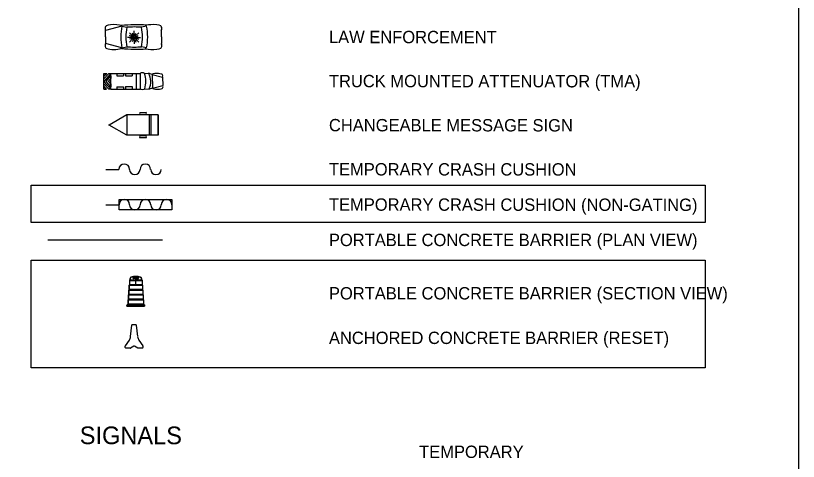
# Model space of a CAD drawing. Extents: x 2486454 to 2490507, y 369321 to 372999.
# Drawn here: x 2488062.6 to 2488506.6, y 370734.3 to 370986.9 of the extents above; entities that cross this region are included whole.
import ezdxf

# ---------------------------------------------------------------- set-up
doc = ezdxf.new("R2010")
doc.units = 0
for name, color, linetype in [('DEV CRASH CUSHION CELL', 7, 'Continuous'), ('Scratch_Level_3', 7, 'Continuous'), ('TC DEV ATTENUATOR', 7, 'Continuous'), ('TC DEV ATTENUATOR TRUCK MOUNTED', 7, 'Continuous'), ('TC DEV BARRIER PCB (UN-ANCHORED)', 7, 'Continuous'), ('TC DEV CMS', 7, 'Continuous'), ('TC DEV LAW ENFORCEMENT', 7, 'Continuous'), ('TC SHEET LAYOUT SHAPE', 7, 'Continuous'), ('TC SHEET TEXT', 7, 'Continuous'), ('TC XS DEVICES', 7, 'Continuous')]:
    doc.layers.add(name, color=color, linetype=linetype)

msp = doc.modelspace()

# ---------------------------------------------------------------- linework, layer by layer
at = {"layer": 'DEV CRASH CUSHION CELL'}
msp.add_line((2488113.69, 370879.76), (2488121.19, 370879.76), dxfattribs=at)
msp.add_lwpolyline([(2488121.19, 370882.76), (2488151.19, 370882.76), (2488151.19, 370876.76), (2488121.19, 370876.76)], close=True, dxfattribs=at)
for centre, start, end in [((2488124.19, 370879.76), 0, 180), ((2488136.19, 370879.76), 0, 180), ((2488148.19, 370879.76), 0, 180), ((2488130.19, 370879.76), 180, 0), ((2488142.19, 370879.76), 180, 0)]:
    msp.add_arc(centre, 3, start, end, dxfattribs=at)
at = {"layer": 'Scratch_Level_3'}
for points in [[(2488071.36, 370890.78), (2488453.76, 370890.78), (2488453.76, 370869.72), (2488071.36, 370869.72)], [(2488071.36, 370848.25), (2488453.76, 370848.25), (2488453.76, 370787.2), (2488071.36, 370787.2)]]:
    msp.add_lwpolyline(points, close=True, dxfattribs=at)
at = {"layer": 'TC DEV ATTENUATOR'}
msp.add_line((2488113.69, 370899.76), (2488121.13, 370899.76), dxfattribs=at)
for centre, radius, start, end in [((2488124.16, 370899.76), 3.03, 359.9999, 179.9999), ((2488130.16, 370899.76), 2.97, 179.9999, 359.9999), ((2488136.13, 370899.76), 3, 359.9999, 179.9999), ((2488142.16, 370899.76), 2.97, 179.9999, 359.9999)]:
    msp.add_arc(centre, radius, start, end, dxfattribs=at)
at = {"layer": 'TC DEV ATTENUATOR TRUCK MOUNTED'}
for p, q in [((2488112.67, 370945.18), (2488112.68, 370954.12)), ((2488112.67, 370951.03), (2488115.44, 370954.12)), ((2488116.64, 370954.12), (2488112.67, 370949.65)), ((2488112.68, 370954.12), (2488112.68, 370952.41)), ((2488112.68, 370954.12), (2488112.68, 370952.41)), ((2488112.68, 370954.12), (2488112.68, 370952.41)), ((2488112.68, 370954.12), (2488112.68, 370952.41)), ((2488112.68, 370952.41), (2488112.68, 370954.12)), ((2488112.68, 370954.12), (2488114.2, 370954.12)), ((2488114.2, 370954.12), (2488112.68, 370952.41)), ((2488113.92, 370949.65), (2488116.64, 370952.73)), ((2488115.44, 370954.12), (2488116.64, 370954.12)), ((2488116.54, 370954.13), (2488133.17, 370954.12)), ((2488116.63, 370945.17), (2488116.64, 370954.12)), ((2488116.64, 370952.73), (2488116.64, 370951.35)), ((2488119.99, 370954.11), (2488119.99, 370952.79)), ((2488119.99, 370952.79), (2488123.74, 370952.79)), ((2488123.74, 370954.1), (2488123.74, 370952.79)), ((2488124.94, 370954.16), (2488124.94, 370952.84)), ((2488124.94, 370952.84), (2488128.68, 370952.84)), ((2488128.69, 370954.15), (2488128.68, 370952.84)), ((2488131, 370954.1), (2488130.99, 370945.16)), ((2488133.17, 370954.12), (2488133.26, 370945.16)), ((2488135.73, 370954.12), (2488137.94, 370954.26)), ((2488139.99, 370953.55), (2488137.94, 370954.26)), ((2488139.97, 370953.55), (2488140.14, 370945.79)), ((2488140, 370953.55), (2488145.82, 370951.94)), ((2488112.67, 370949.65), (2488112.67, 370951.03)), ((2488112.67, 370949.65), (2488116.63, 370945.17)), ((2488112.67, 370948.31), (2488112.67, 370949.65)), ((2488115.43, 370945.18), (2488112.67, 370948.31)), ((2488116.63, 370946.6), (2488113.92, 370949.65)), ((2488116.64, 370951.35), (2488115.12, 370949.65)), ((2488115.16, 370949.65), (2488116.64, 370947.99)), ((2488116.64, 370947.99), (2488116.63, 370946.6)), ((2488145.82, 370951.94), (2488145.97, 370947.38)), ((2488112.67, 370946.88), (2488112.67, 370945.18)), ((2488114.19, 370945.18), (2488112.67, 370946.88)), ((2488112.67, 370945.18), (2488114.19, 370945.18)), ((2488116.63, 370945.17), (2488115.43, 370945.18)), ((2488116.63, 370945.17), (2488133.26, 370945.16)), ((2488119.99, 370946.6), (2488123.73, 370946.6)), ((2488119.99, 370946.6), (2488119.99, 370945.17)), ((2488123.73, 370946.6), (2488123.73, 370945.17)), ((2488124.93, 370946.65), (2488128.68, 370946.65)), ((2488124.93, 370946.65), (2488124.93, 370945.22)), ((2488128.68, 370946.65), (2488128.68, 370945.22)), ((2488135.78, 370945.45), (2488138.21, 370945.23)), ((2488140.14, 370945.79), (2488138.21, 370945.23)), ((2488140.14, 370945.79), (2488145.97, 370947.38))]:
    msp.add_line(p, q, dxfattribs=at)
for centre, radius, start, end in [((2488121.08, 370949.71), 15.3, 343.8365, 16.7472), ((2488129.69, 370949.49), 9.52, 333.4445, 30.0214), ((2488144.38, 370952.71), 1.61, 331.8365, 28.0763), ((2488144.54, 370946.62), 1.61, 331.8365, 28.0763)]:
    msp.add_arc(centre, radius, start, end, dxfattribs=at)
for centre, major_axis, ratio, start_param, end_param in [((2488134.46, 370954.12), (1.27, 0), 0.269913, 0, 3.141593), ((2488142.9, 370953.51), (2.91, -0.04), 0.2034, 0, 3.141593), ((2488134.52, 370945.45), (1.26, 0), 0.27366, 3.141593, 6.283185), ((2488143.05, 370945.82), (2.91, 0.03), 0.2034, 3.141593, 6.283185)]:
    msp.add_ellipse(centre, major_axis=major_axis, ratio=ratio, start_param=start_param, end_param=end_param, dxfattribs=at)
at = {"layer": 'TC DEV BARRIER PCB (UN-ANCHORED)'}
msp.add_line((2488080.83, 370859.79), (2488145.94, 370859.79), dxfattribs=at)
at = {"layer": 'TC DEV CMS'}
for p, q in [((2488125.56, 370930.62), (2488115.6, 370924.84)), ((2488143.41, 370930.66), (2488125.56, 370930.62)), ((2488125.56, 370930.62), (2488125.59, 370919.1)), ((2488136.67, 370931.92), (2488132.98, 370931.91)), ((2488136.67, 370930.87), (2488132.98, 370930.87)), ((2488138.28, 370930.65), (2488138.3, 370919.12)), ((2488139.24, 370930.66), (2488139.26, 370919.12)), ((2488139.24, 370930.66), (2488139.26, 370919.12)), ((2488143.41, 370930.66), (2488143.43, 370919.13)), ((2488143.43, 370919.12), (2488143.41, 370930.66)), ((2488125.59, 370919.1), (2488115.6, 370924.84)), ((2488143.43, 370919.13), (2488125.59, 370919.1)), ((2488136.69, 370918.75), (2488133.01, 370918.75)), ((2488136.69, 370917.66), (2488133.01, 370917.66))]:
    msp.add_line(p, q, dxfattribs=at)
msp.add_circle((2488115.49, 370924.85), 0.102, dxfattribs=at)
for centre, start, end in [((2488133.65, 370931.39), 142.1962, 218.0195), ((2488136, 370931.4), 322.1962, 38.0195), ((2488133.68, 370918.23), 142.1962, 218.0195), ((2488136.02, 370918.23), 322.1962, 38.0195)]:
    msp.add_arc(centre, 0.851, start, end, dxfattribs=at)
at = {"layer": 'TC DEV LAW ENFORCEMENT'}
for p, q in [((2488122.85, 370980.94), (2488113.6, 370978.41)), ((2488122.85, 370980.94), (2488125.71, 370980.33)), ((2488136.82, 370980.94), (2488133.96, 370980.33)), ((2488136, 370981.11), (2488136, 370980.77)), ((2488113.6, 370974.8), (2488113.6, 370978.41)), ((2488113.6, 370974.8), (2488113.6, 370971.17)), ((2488128.72, 370975.61), (2488127.12, 370977.21)), ((2488128.41, 370975.13), (2488127.21, 370975.63)), ((2488129.2, 370975.92), (2488128.78, 370976.93)), ((2488129.76, 370976.03), (2488129.76, 370978.3)), ((2488130.31, 370975.92), (2488130.79, 370977.06)), ((2488130.78, 370975.6), (2488132.39, 370977.2)), ((2488131.06, 370975.11), (2488132.14, 370975.56)), ((2488145.22, 370974.8), (2488145.22, 370978.41)), ((2488145.22, 370974.8), (2488145.22, 370971.17)), ((2488122.85, 370968.64), (2488113.6, 370971.17)), ((2488128.3, 370974.58), (2488126.02, 370974.58)), ((2488128.72, 370973.55), (2488127.11, 370971.94)), ((2488128.4, 370974.02), (2488127.23, 370973.53)), ((2488129.19, 370973.23), (2488128.68, 370972)), ((2488129.75, 370973.12), (2488129.75, 370970.85)), ((2488130.31, 370973.23), (2488130.83, 370971.95)), ((2488130.78, 370973.54), (2488132.38, 370971.93)), ((2488131.01, 370974.05), (2488132.27, 370973.52)), ((2488131.21, 370974.57), (2488133.48, 370974.57)), ((2488122.85, 370968.64), (2488125.71, 370969.26)), ((2488136.82, 370968.64), (2488133.96, 370969.26)), ((2488136, 370968.83), (2488136, 370968.49))]:
    msp.add_line(p, q, dxfattribs=at)
for radius in [1.14, 1.01, 0.425]:
    msp.add_circle((2488129.75, 370974.57), radius, dxfattribs=at)
for centre, radius, start, end in [((2488115.88, 370979.61), 2.56, 151.8799, 208.1198), ((2488151.38, 370974.79), 29.18, 167.8323, 192.1675), ((2488130.82, 370910.06), 71.67, 85.1528, 96.5948), ((2488151.38, 370974.79), 26.26, 167.8323, 192.1675), ((2488129.83, 370922.54), 57.93, 85.9178, 94.0819), ((2488108.29, 370974.79), 26.26, 347.8323, 12.1675), ((2488108.29, 370974.79), 29.18, 347.8323, 12.1675), ((2488142.94, 370979.61), 2.56, 331.8799, 28.1198), ((2488115.88, 370969.96), 2.56, 151.8799, 208.1198), ((2488142.94, 370969.96), 2.56, 331.8799, 28.1198), ((2488130.82, 371039.54), 71.67, 263.405, 274.7374), ((2488129.83, 371029.75), 60.63, 266.0999, 273.8998)]:
    msp.add_arc(centre, radius, start, end, dxfattribs=at)
for centre, major_axis, start_param, end_param in [((2488118.24, 370980.87), (-4.61, -0.05), 3.141593, 6.283185), ((2488140.58, 370980.87), (4.61, -0.05), 0, 2.945373), ((2488118.24, 370968.7), (-4.61, 0.05), 0, 3.141593), ((2488140.58, 370968.7), (4.61, 0.05), 3.331712, 6.283185)]:
    msp.add_ellipse(centre, major_axis=major_axis, ratio=0.2034, start_param=start_param, end_param=end_param, dxfattribs=at)
at = {"layer": 'TC SHEET LAYOUT SHAPE'}
msp.add_lwpolyline([(2487016.56, 370666.84), (2487016.56, 370976.16), (2487016.56, 371248.27), (2487026.56, 371258.27), (2487469.58, 371258.27), (2487940.56, 371258.27), (2488261.56, 371258.27), (2488261.56, 371178.27), (2488346.56, 371178.27), (2488346.56, 371226.27), (2488506.56, 371226.27), (2488506.56, 370891.3), (2488506.56, 370612.1), (2488506.56, 370360.77), (2487778.38, 370360.77), (2487778.38, 370218.27), (2487608.92, 370218.27), (2487256.14, 370218.27), (2487016.56, 370218.27)], close=True, dxfattribs=at)
at = {"layer": 'TC XS DEVICES'}
for p, q in [((2488127.59, 370837.21), (2488127.59, 370837.94)), ((2488127.59, 370837.21), (2488133.86, 370837.21)), ((2488129.16, 370838.17), (2488129.16, 370838.21)), ((2488132.29, 370838.17), (2488132.29, 370838.21)), ((2488133.86, 370837.21), (2488133.86, 370837.94)), ((2488127.06, 370834.46), (2488126.88, 370834.07)), ((2488126.88, 370834.07), (2488126.88, 370831.72)), ((2488126.88, 370834.07), (2488134.57, 370834.07)), ((2488127.06, 370836.82), (2488127.06, 370834.46)), ((2488127.06, 370836.82), (2488134.39, 370836.82)), ((2488127.06, 370834.46), (2488134.39, 370834.46)), ((2488134.39, 370836.82), (2488134.39, 370834.46)), ((2488134.39, 370834.46), (2488134.57, 370834.07)), ((2488134.57, 370834.07), (2488134.57, 370831.72)), ((2488126.7, 370828.97), (2488126.52, 370828.58)), ((2488126.52, 370828.58), (2488134.93, 370828.58)), ((2488126.52, 370828.58), (2488126.52, 370826.23)), ((2488126.88, 370831.72), (2488126.7, 370831.33)), ((2488126.7, 370831.33), (2488134.75, 370831.33)), ((2488126.7, 370831.33), (2488126.7, 370828.97)), ((2488126.7, 370828.97), (2488134.75, 370828.97)), ((2488126.88, 370831.72), (2488134.57, 370831.72)), ((2488134.57, 370831.72), (2488134.75, 370831.33)), ((2488134.75, 370831.33), (2488134.75, 370828.97)), ((2488134.75, 370828.97), (2488134.93, 370828.58)), ((2488134.93, 370828.58), (2488134.93, 370826.23)), ((2488126.52, 370826.23), (2488126.35, 370825.84)), ((2488126.35, 370825.84), (2488135.1, 370825.84)), ((2488126.35, 370825.84), (2488126.35, 370823.48)), ((2488126.52, 370826.23), (2488134.93, 370826.23)), ((2488134.93, 370826.23), (2488135.1, 370825.84)), ((2488135.1, 370825.84), (2488135.1, 370823.48)), ((2488125.72, 370822.31), (2488125.72, 370822.7)), ((2488125.72, 370822.31), (2488135.72, 370822.31)), ((2488126.12, 370823.09), (2488135.33, 370823.09)), ((2488126.35, 370823.48), (2488126.17, 370823.09)), ((2488126.35, 370823.48), (2488135.1, 370823.48)), ((2488135.1, 370823.48), (2488135.28, 370823.09)), ((2488135.72, 370822.31), (2488135.72, 370822.7)), ((2488127.8, 370804.99), (2488128.43, 370811.55)), ((2488127.8, 370804.99), (2488128.43, 370811.55)), ((2488128.75, 370811.83), (2488130.69, 370811.83)), ((2488128.75, 370811.83), (2488130.69, 370811.83)), ((2488131, 370811.55), (2488131.74, 370804.96)), ((2488131, 370811.55), (2488131.74, 370804.96)), ((2488124.83, 370799.82), (2488127.06, 370803)), ((2488124.83, 370799.82), (2488127.06, 370803)), ((2488132.47, 370803.03), (2488134.72, 370799.82)), ((2488132.47, 370803.03), (2488134.72, 370799.82)), ((2488124.78, 370798.8), (2488124.78, 370799.64)), ((2488124.78, 370798.8), (2488124.78, 370799.64)), ((2488127.61, 370798.48), (2488125.09, 370798.48)), ((2488127.61, 370798.48), (2488125.09, 370798.48)), ((2488134.46, 370798.48), (2488131.95, 370798.48)), ((2488134.46, 370798.48), (2488131.95, 370798.48)), ((2488134.78, 370799.64), (2488134.78, 370798.8)), ((2488134.78, 370799.64), (2488134.78, 370798.8))]:
    msp.add_line(p, q, dxfattribs=at)
for points in [[(2488126.88, 370834.07), (2488130.72, 370834.07), (2488130.72, 370837.99), (2488130.53, 370837.99), (2488130.39, 370837.99), (2488130.24, 370837.98), (2488130.08, 370837.97), (2488129.91, 370837.96), (2488129.74, 370837.94), (2488129.55, 370837.91), (2488129.42, 370837.9), (2488129.35, 370837.91), (2488129.29, 370837.94), (2488129.24, 370837.98), (2488129.2, 370838.03), (2488129.17, 370838.08), (2488129.16, 370838.13), (2488129.16, 370838.24), (2488129.17, 370838.3), (2488129.21, 370838.37), (2488129.26, 370838.42), (2488129.33, 370838.46), (2488129.39, 370838.48), (2488129.53, 370838.5), (2488129.72, 370838.52), (2488130.12, 370838.56), (2488130.4, 370838.57), (2488130.61, 370838.58), (2488130.72, 370838.58), (2488130.72, 370839.07), (2488130.52, 370839.07), (2488130.25, 370839.06), (2488129.99, 370839.05), (2488129.7, 370839.02), (2488129.43, 370838.98), (2488129.14, 370838.93), (2488128.8, 370838.86), (2488128.6, 370838.82), (2488128.28, 370838.73), (2488128.14, 370838.69), (2488128.06, 370838.66), (2488127.96, 370838.61), (2488127.87, 370838.55), (2488127.78, 370838.45), (2488127.71, 370838.36), (2488127.66, 370838.27), (2488127.62, 370838.17), (2488127.6, 370838.07), (2488127.59, 370837.94), (2488127.59, 370837.21), (2488127.52, 370837.18), (2488127.44, 370837.14), (2488127.35, 370837.08), (2488127.25, 370837.01), (2488127.17, 370836.94), (2488127.06, 370836.82), (2488127.06, 370834.46)], [(2488134.57, 370834.07), (2488130.72, 370834.07), (2488130.72, 370837.99), (2488131.05, 370837.99), (2488131.28, 370837.97), (2488131.48, 370837.96), (2488131.65, 370837.94), (2488131.83, 370837.92), (2488131.98, 370837.9), (2488132.05, 370837.9), (2488132.11, 370837.91), (2488132.18, 370837.96), (2488132.24, 370838.01), (2488132.28, 370838.07), (2488132.29, 370838.13), (2488132.29, 370838.21), (2488132.28, 370838.3), (2488132.24, 370838.37), (2488132.2, 370838.42), (2488132.15, 370838.45), (2488132.11, 370838.47), (2488132.06, 370838.48), (2488131.93, 370838.5), (2488131.79, 370838.51), (2488131.66, 370838.53), (2488131.52, 370838.54), (2488131.35, 370838.56), (2488131.16, 370838.57), (2488131.01, 370838.58), (2488130.88, 370838.58), (2488130.72, 370838.58), (2488130.72, 370839.07), (2488130.95, 370839.07), (2488131.13, 370839.06), (2488131.38, 370839.05), (2488131.56, 370839.04), (2488131.75, 370839.02), (2488131.96, 370838.99), (2488132.21, 370838.95), (2488132.46, 370838.9), (2488132.75, 370838.84), (2488133, 370838.78), (2488133.21, 370838.72), (2488133.31, 370838.69), (2488133.4, 370838.66), (2488133.48, 370838.61), (2488133.58, 370838.55), (2488133.64, 370838.49), (2488133.71, 370838.41), (2488133.76, 370838.33), (2488133.81, 370838.23), (2488133.83, 370838.15), (2488133.85, 370838.05), (2488133.86, 370837.98), (2488133.86, 370837.94), (2488133.86, 370837.21), (2488134.01, 370837.14), (2488134.08, 370837.09), (2488134.15, 370837.04), (2488134.23, 370836.98), (2488134.32, 370836.9), (2488134.36, 370836.85), (2488134.39, 370836.82), (2488134.39, 370834.46)], [(2488126.88, 370834.07), (2488134.57, 370834.07), (2488134.57, 370831.72), (2488126.88, 370831.72)], [(2488126.88, 370831.72), (2488134.57, 370831.72), (2488134.75, 370831.33), (2488134.75, 370828.97), (2488134.93, 370828.58), (2488126.52, 370828.58), (2488126.7, 370828.97), (2488126.7, 370831.33)], [(2488126.52, 370828.58), (2488134.93, 370828.58), (2488134.93, 370826.23), (2488126.52, 370826.23)], [(2488126.52, 370826.23), (2488134.93, 370826.23), (2488135.1, 370825.84), (2488135.1, 370823.48), (2488135.28, 370823.09), (2488135.38, 370823.09), (2488135.44, 370823.08), (2488135.51, 370823.05), (2488135.58, 370823.01), (2488135.62, 370822.97), (2488135.67, 370822.91), (2488135.7, 370822.84), (2488135.71, 370822.79), (2488135.73, 370822.74), (2488135.72, 370822.7), (2488135.72, 370822.31), (2488125.72, 370822.31), (2488125.72, 370822.7), (2488125.73, 370822.76), (2488125.74, 370822.82), (2488125.77, 370822.88), (2488125.8, 370822.92), (2488125.83, 370822.96), (2488125.88, 370823.01), (2488125.94, 370823.05), (2488126.01, 370823.08), (2488126.05, 370823.09), (2488126.12, 370823.09), (2488126.17, 370823.09), (2488126.35, 370823.48), (2488126.35, 370825.84)]]:
    msp.add_lwpolyline(points, close=True, dxfattribs=at)
for points in [[(2488129.61, 370799.64), (2488127.77, 370798.53)], [(2488129.61, 370799.64), (2488127.77, 370798.53)], [(2488131.78, 370798.53), (2488129.94, 370799.64)], [(2488131.78, 370798.53), (2488129.94, 370799.64)]]:
    msp.add_lwpolyline(points, dxfattribs=at)
for centre, radius, start, end in [((2488128.1, 370835.95), 1.36, 112.306, 140.5136), ((2488128.37, 370837.94), 0.784, 106.9492, 180), ((2488130.72, 370830.22), 8.85, 73.0508, 106.9492), ((2488129.43, 370838.21), 0.274, 98.674, 180), ((2488129.43, 370838.17), 0.274, 180, 278.1488), ((2488130.72, 370829.73), 8.85, 81.326, 98.674), ((2488130.72, 370829.14), 8.85, 81.8513, 98.1488), ((2488132.02, 370838.17), 0.274, 261.8513, 0), ((2488132.02, 370838.21), 0.274, 0, 81.326), ((2488133.08, 370837.94), 0.784, 0, 73.0508), ((2488133.35, 370835.95), 1.36, 39.4865, 67.694), ((2488126.12, 370822.7), 0.392, 90, 180), ((2488135.33, 370822.7), 0.392, 0, 90), ((2488128.75, 370811.52), 0.312, 90, 173.5781), ((2488128.75, 370811.52), 0.312, 90, 173.5781), ((2488130.69, 370811.52), 0.312, 6.4219, 90), ((2488130.69, 370811.52), 0.312, 6.4219, 90), ((2488123.65, 370805.39), 4.17, 325.008, 354.4565), ((2488123.65, 370805.39), 4.17, 325.008, 354.4565), ((2488135.88, 370805.42), 4.17, 186.4219, 214.992), ((2488135.88, 370805.42), 4.17, 186.4219, 214.992), ((2488125.09, 370799.64), 0.313, 145.008, 180), ((2488125.09, 370799.64), 0.313, 145.008, 180), ((2488125.09, 370798.8), 0.312, 180, 270), ((2488125.09, 370798.8), 0.312, 180, 270), ((2488127.61, 370798.8), 0.312, 270, 300.9638), ((2488127.61, 370798.8), 0.312, 270, 300.9638), ((2488129.78, 370799.37), 0.313, 59.0362, 120.9638), ((2488129.78, 370799.37), 0.313, 59.0362, 120.9638), ((2488131.95, 370798.8), 0.313, 239.0362, 270), ((2488131.95, 370798.8), 0.313, 239.0362, 270), ((2488134.46, 370798.8), 0.313, 270, 360), ((2488134.46, 370798.8), 0.313, 270, 360), ((2488134.46, 370799.64), 0.312, 0, 34.992), ((2488134.46, 370799.64), 0.312, 0, 34.992)]:
    msp.add_arc(centre, radius, start, end, dxfattribs=at)

# ---------------------------------------------------------------- texts
at = {"layer": 'TC SHEET TEXT'}
for s, height, rotation, p in [('LAW ENFORCEMENT', 7, 359.9597, (2488240.29, 370971.32)), ('TRUCK MOUNTED ATTENUATOR (TMA)', 7, 359.9597, (2488240.29, 370946.35)), ('CHANGEABLE MESSAGE SIGN', 7, 359.9597, (2488240.29, 370921.34)), ('TEMPORARY CRASH CUSHION', 7, 359.9597, (2488240.29, 370896.34)), ('TEMPORARY CRASH CUSHION (NON-GATING)', 7, 359.9597, (2488240.29, 370876.35)), ('PORTABLE CONCRETE BARRIER (PLAN VIEW)', 7, 360, (2488240.29, 370856.29)), ('PORTABLE CONCRETE BARRIER (SECTION VIEW)', 7, 360, (2488240.29, 370826.04)), ('ANCHORED CONCRETE BARRIER (RESET)', 7, 360, (2488240.29, 370800.79)), ('SIGNALS', 10, 359.9597, (2488098.93, 370744.04)), ('TEMPORARY ', 7, 359.9597, (2488291.44, 370736.22))]:
    msp.add_text(s, height=height, rotation=rotation, dxfattribs=at).set_placement(p)

doc.saveas('drawing.dxf')
